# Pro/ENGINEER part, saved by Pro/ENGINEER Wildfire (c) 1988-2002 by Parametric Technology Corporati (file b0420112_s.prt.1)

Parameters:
  HERSTELLER = "Hersteller"
  NB = "B0420112_s"
  NN = "B01"
  NT = "Straight Roller"
  NBSYN = "$PN."
  LINA = "B0420112_s"
  PN = "B0420112_s"
  PN1 = "0420112_s"
  HUB = "2-3/16"
  BORE = "1-3/16"
  BEARING = "3/4"
  H = "2.308"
